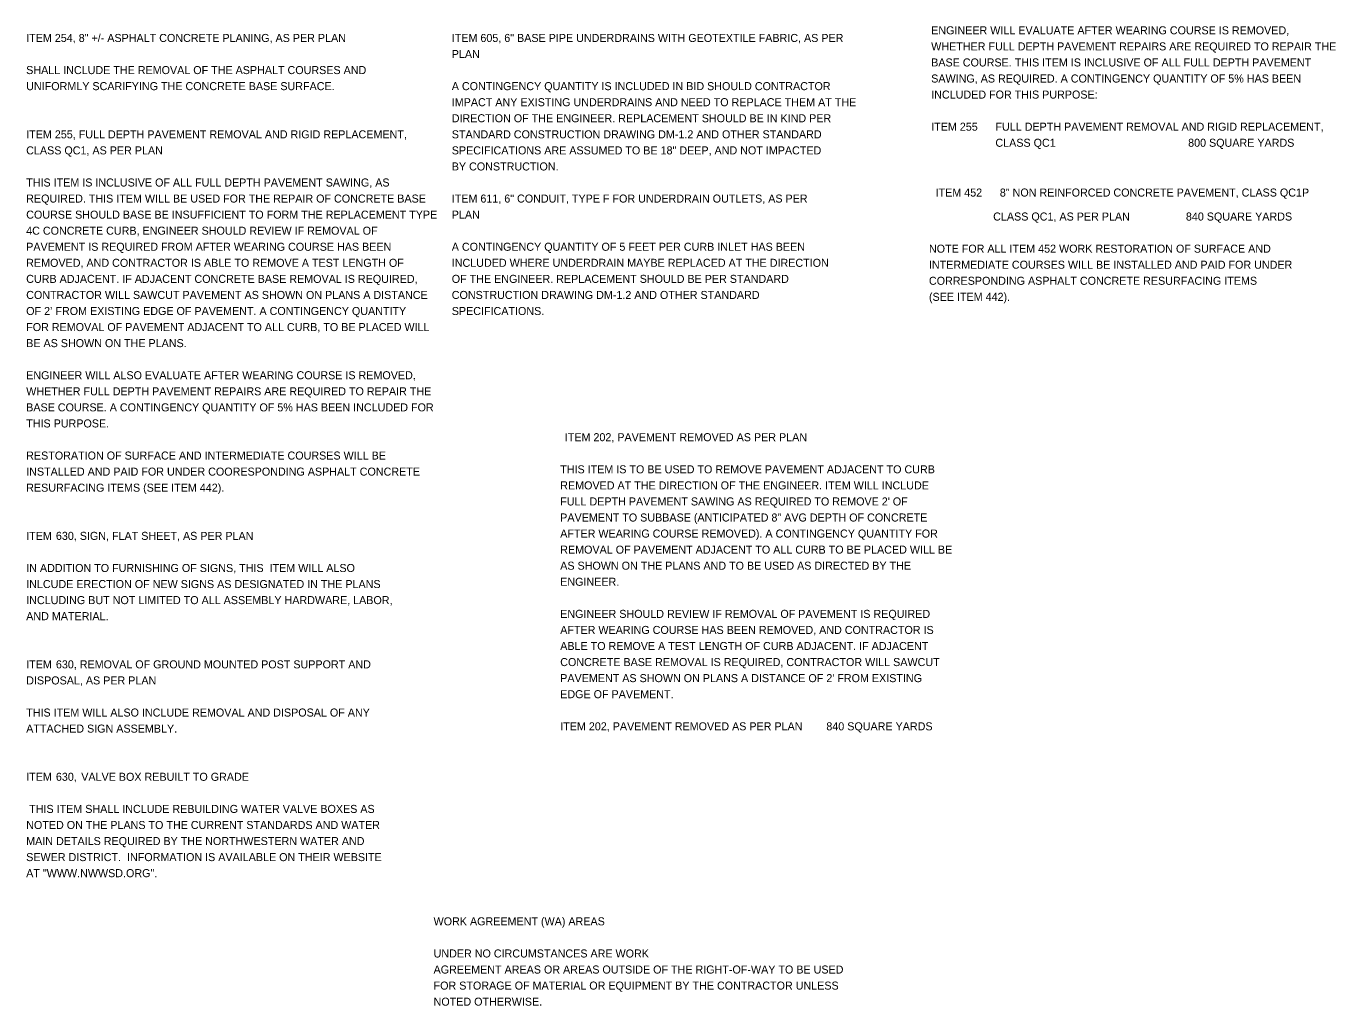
# Model space of a CAD drawing. Extents: x -25 to 34, y -0.5 to 22.
# Drawn here: x -24.99 to -2.16, y 3.66 to 20.74 of the extents above; entities that cross this region are included whole.
import ezdxf

# ---------------------------------------------------------------- set-up
doc = ezdxf.new("R2010")
doc.units = 0
doc.layers.add('SH_Text', color=7, linetype='Continuous')

msp = doc.modelspace()

# ---------------------------------------------------------------- texts
at = {"layer": 'SH_Text'}
for s, p in [('ITEM 254, 8" +/- ASPHALT CONCRETE PLANING, AS PER PLAN ', (-24.994, 20.461)), ('ITEM 605, 6" BASE PIPE UNDERDRAINS WITH GEOTEXTILE FABRIC, AS PER', (-17.574, 20.461)), ('ENGINEER WILL EVALUATE AFTER WEARING COURSE IS REMOVED,', (-9.215, 20.594)), ('WHETHER FULL DEPTH PAVEMENT REPAIRS ARE REQUIRED TO REPAIR THE', (-9.215, 20.314)), ('PLAN', (-17.574, 20.181)), ('BASE COURSE. THIS ITEM IS INCLUSIVE OF ALL FULL DEPTH PAVEMENT', (-9.215, 20.034)), ('SHALL INCLUDE THE REMOVAL OF THE ASPHALT COURSES AND ', (-24.994, 19.901)), ('SAWING, AS REQUIRED. A CONTINGENCY QUANTITY OF 5% HAS BEEN', (-9.215, 19.754)), ('UNIFORMLY SCARIFYING THE CONCRETE BASE SURFACE.', (-24.994, 19.621)), ('A CONTINGENCY QUANTITY IS INCLUDED IN BID SHOULD CONTRACTOR', (-17.574, 19.621)), ('IMPACT ANY EXISTING UNDERDRAINS AND NEED TO REPLACE THEM AT THE', (-17.574, 19.341)), ('INCLUDED FOR THIS PURPOSE:', (-9.215, 19.474)), ('DIRECTION OF THE ENGINEER. REPLACEMENT SHOULD BE IN KIND PER', (-17.574, 19.061)), ('ITEM 255', (-9.215, 18.914)), ('FULL DEPTH PAVEMENT REMOVAL AND RIGID REPLACEMENT,', (-8.095, 18.914)), ('ITEM 255, FULL DEPTH PAVEMENT REMOVAL AND RIGID REPLACEMENT,', (-24.994, 18.781)), ('STANDARD CONSTRUCTION DRAWING DM-1.2 AND OTHER STANDARD', (-17.574, 18.781)), ('CLASS QC1', (-8.095, 18.634)), ('800 SQUARE YARDS', (-4.735, 18.634)), ('CLASS QC1, AS PER PLAN', (-24.994, 18.501)), ('SPECIFICATIONS ARE ASSUMED TO BE 18" DEEP, AND NOT IMPACTED ', (-17.574, 18.501)), ('BY CONSTRUCTION. ', (-17.574, 18.221)), ('THIS ITEM IS INCLUSIVE OF ALL FULL DEPTH PAVEMENT SAWING, AS', (-24.994, 17.941)), ('ITEM 452', (-9.138, 17.766)), ('8" NON REINFORCED CONCRETE PAVEMENT, CLASS QC1P', (-8.018, 17.766)), ('REQUIRED. THIS ITEM WILL BE USED FOR THE REPAIR OF CONCRETE BASE', (-24.994, 17.661)), ('ITEM 611, 6" CONDUIT, TYPE F FOR UNDERDRAIN OUTLETS, AS PER', (-17.574, 17.661)), ('COURSE SHOULD BASE BE INSUFFICIENT TO FORM THE REPLACEMENT TYPE', (-24.994, 17.381)), ('PLAN', (-17.574, 17.381)), ('CLASS QC1, AS PER PLAN', (-8.134, 17.348)), ('840 SQUARE YARDS', (-4.774, 17.348)), ('4C CONCRETE CURB, ENGINEER SHOULD REVIEW IF REMOVAL OF', (-24.994, 17.101)), ('PAVEMENT IS REQUIRED FROM AFTER WEARING COURSE HAS BEEN', (-24.994, 16.821)), ('A CONTINGENCY QUANTITY OF 5 FEET PER CURB INLET HAS BEEN', (-17.574, 16.821)), ('NOTE FOR ALL ITEM 452 WORK RESTORATION OF SURFACE AND', (-9.254, 16.788)), ('REMOVED, AND CONTRACTOR IS ABLE TO REMOVE A TEST LENGTH OF', (-24.994, 16.541)), ('INCLUDED WHERE UNDERDRAIN MAYBE REPLACED AT THE DIRECTION', (-17.574, 16.541)), ('INTERMEDIATE COURSES WILL BE INSTALLED AND PAID FOR UNDER', (-9.254, 16.508)), ('CURB ADJACENT. IF ADJACENT CONCRETE BASE REMOVAL IS REQUIRED,', (-24.994, 16.261)), ('OF THE ENGINEER. REPLACEMENT SHOULD BE PER STANDARD', (-17.574, 16.261)), ('CORRESPONDING ASPHALT CONCRETE RESURFACING ITEMS', (-9.254, 16.228)), ('CONTRACTOR WILL SAWCUT PAVEMENT AS SHOWN ON PLANS A DISTANCE', (-24.994, 15.981)), ('CONSTRUCTION DRAWING DM-1.2 AND OTHER STANDARD', (-17.574, 15.981)), ('(SEE ITEM 442).', (-9.254, 15.948)), ('OF 2’ FROM EXISTING EDGE OF PAVEMENT. A CONTINGENCY QUANTITY', (-24.994, 15.701)), ('SPECIFICATIONS.', (-17.574, 15.701)), ('FOR REMOVAL OF PAVEMENT ADJACENT TO ALL CURB, TO BE PLACED WILL', (-24.994, 15.421)), ('BE AS SHOWN ON THE PLANS.', (-24.994, 15.141)), ('ENGINEER WILL ALSO EVALUATE AFTER WEARING COURSE IS REMOVED,', (-24.994, 14.581)), ('WHETHER FULL DEPTH PAVEMENT REPAIRS ARE REQUIRED TO REPAIR THE', (-24.994, 14.301)), ('BASE COURSE. A CONTINGENCY QUANTITY OF 5% HAS BEEN INCLUDED FOR', (-24.994, 14.021)), ('THIS PURPOSE.', (-24.994, 13.741)), ('ITEM 202, PAVEMENT REMOVED AS PER PLAN ', (-15.603, 13.501)), ('RESTORATION OF SURFACE AND INTERMEDIATE COURSES WILL BE', (-24.994, 13.181)), ('INSTALLED AND PAID FOR UNDER COORESPONDING ASPHALT CONCRETE', (-24.994, 12.901)), ('THIS ITEM IS TO BE USED TO REMOVE PAVEMENT ADJACENT TO CURB', (-15.683, 12.941)), ('REMOVED AT THE DIRECTION OF THE ENGINEER. ITEM WILL INCLUDE', (-15.683, 12.661)), ('RESURFACING ITEMS (SEE ITEM 442).', (-24.994, 12.621)), ("FULL DEPTH PAVEMENT SAWING AS REQUIRED TO REMOVE 2' OF", (-15.683, 12.381)), ('PAVEMENT TO SUBBASE (ANTICIPATED 8" AVG DEPTH OF CONCRETE', (-15.683, 12.101)), ('ITEM ', (-24.994, 11.781)), ('630, SIGN, FLAT SHEET, AS PER PLAN', (-24.476, 11.781)), ('AFTER WEARING COURSE REMOVED). A CONTINGENCY QUANTITY FOR', (-15.683, 11.821)), ('REMOVAL OF PAVEMENT ADJACENT TO ALL CURB TO BE PLACED WILL BE', (-15.683, 11.541)), ('IN ADDITION TO FURNISHING OF SIGNS, THIS  ITEM WILL ALSO ', (-24.994, 11.221)), ('AS SHOWN ON THE PLANS AND TO BE USED AS DIRECTED BY THE', (-15.683, 11.261)), ('INLCUDE ERECTION OF NEW SIGNS AS DESIGNATED IN THE PLANS ', (-24.994, 10.941)), ('ENGINEER.', (-15.683, 10.981)), ('INCLUDING BUT NOT LIMITED TO ALL ASSEMBLY HARDWARE, LABOR, ', (-24.994, 10.661)), ('AND MATERIAL.', (-24.994, 10.381)), ('ENGINEER SHOULD REVIEW IF REMOVAL OF PAVEMENT IS REQUIRED', (-15.683, 10.421)), ('AFTER WEARING COURSE HAS BEEN REMOVED, AND CONTRACTOR IS', (-15.683, 10.141)), ('ABLE TO REMOVE A TEST LENGTH OF CURB ADJACENT. IF ADJACENT', (-15.683, 9.861)), ('ITEM ', (-24.994, 9.541)), ('630, REMOVAL OF GROUND MOUNTED POST SUPPORT AND ', (-24.476, 9.541)), ('CONCRETE BASE REMOVAL IS REQUIRED, CONTRACTOR WILL SAWCUT', (-15.683, 9.581)), ('DISPOSAL, AS PER PLAN  ', (-24.994, 9.261)), ("PAVEMENT AS SHOWN ON PLANS A DISTANCE OF 2' FROM EXISTING", (-15.683, 9.301)), ('EDGE OF PAVEMENT.', (-15.683, 9.021)), ('THIS ITEM WILL ALSO INCLUDE REMOVAL AND DISPOSAL OF ANY ', (-24.994, 8.701)), ('ATTACHED SIGN ASSEMBLY.', (-24.994, 8.421)), ('ITEM 202, PAVEMENT REMOVED AS PER PLAN        840 SQUARE YARDS', (-15.683, 8.461)), ('ITEM ', (-24.994, 7.581)), ('630, ', (-24.476, 7.581)), ('VALVE BOX REBUILT TO GRADE', (-24.034, 7.581)), (' THIS ITEM SHALL INCLUDE REBUILDING WATER VALVE BOXES AS ', (-24.994, 7.021)), ('NOTED ON THE PLANS TO THE CURRENT STANDARDS AND WATER ', (-24.994, 6.741)), ('MAIN DETAILS REQUIRED BY THE NORTHWESTERN WATER AND ', (-24.994, 6.461)), ('SEWER DISTRICT.  INFORMATION IS AVAILABLE ON THEIR WEBSITE', (-24.994, 6.181)), ('AT "WWW.NWWSD.ORG".', (-24.994, 5.901)), ('WORK AGREEMENT (WA) AREAS', (-17.891, 5.061)), ('UNDER NO CIRCUMSTANCES ARE WORK', (-17.891, 4.501)), ('AGREEMENT AREAS OR AREAS OUTSIDE OF THE RIGHT-OF-WAY TO BE USED', (-17.891, 4.221)), ('FOR STORAGE OF MATERIAL OR EQUIPMENT BY THE CONTRACTOR UNLESS', (-17.891, 3.941)), ('NOTED OTHERWISE.', (-17.891, 3.661))]:
    msp.add_text(s, height=0.14, dxfattribs=at).set_placement(p)

doc.saveas('drawing.dxf')
